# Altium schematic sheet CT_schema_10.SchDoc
size 251 x 159 mm
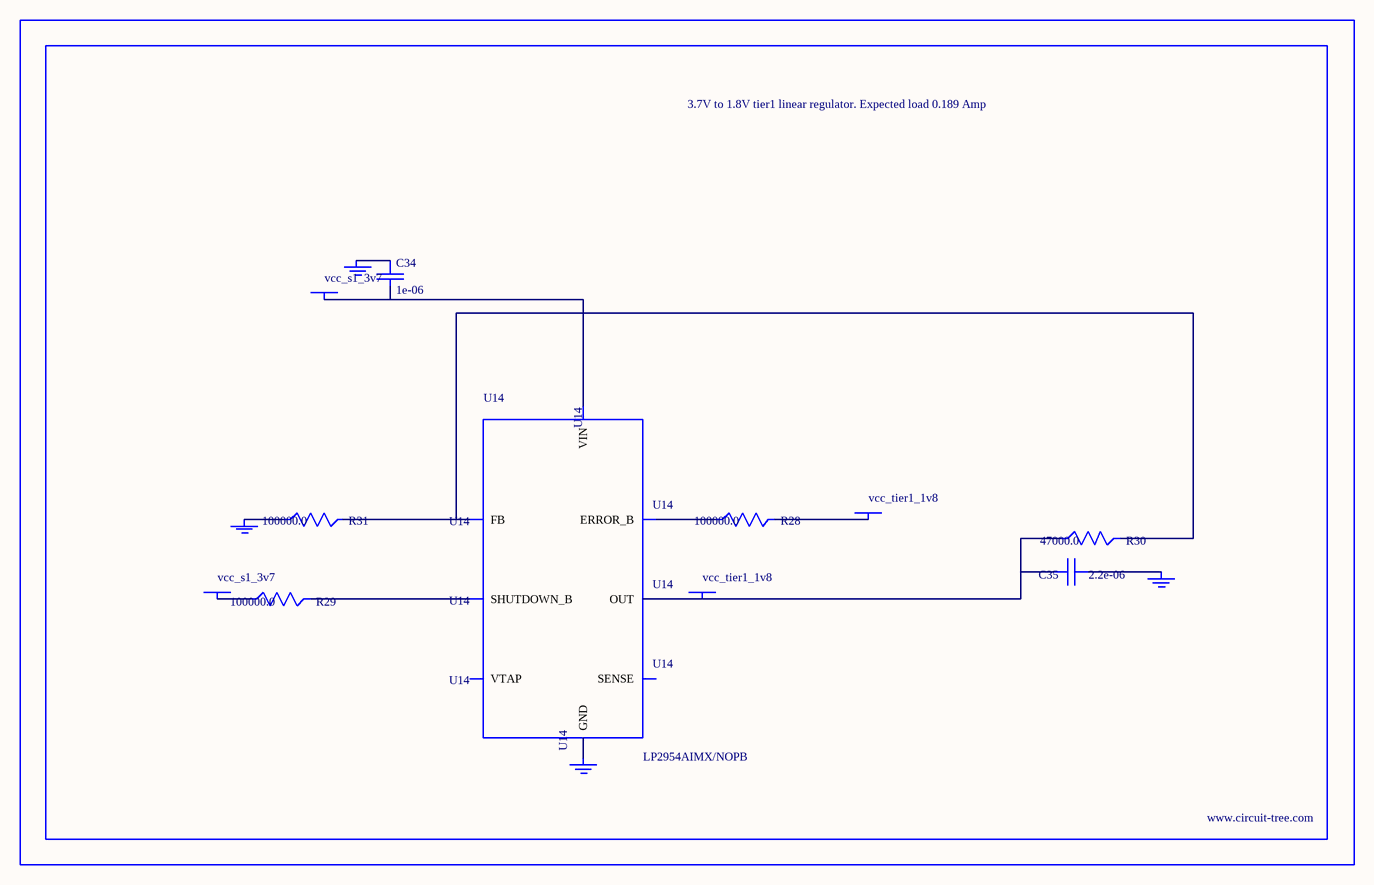
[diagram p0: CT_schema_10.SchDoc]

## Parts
BORDER9  (no value)
C34  1e-06  [EXV-9B]
C35  2.2e-06  [EXV-9B]
GND_INSTANCE_9_0  (no value)
GND_INSTANCE_9_1  (no value)
GND_INSTANCE_9_2  (no value)
GND_INSTANCE_9_3  (no value)
POWER_INSTANCE_9_0  vcc_s1_3v7
POWER_INSTANCE_9_1  vcc_tier1_1v8
POWER_INSTANCE_9_2  vcc_s1_3v7
POWER_INSTANCE_9_3  vcc_tier1_1v8
R28  100000.0  [R0603]
R29  100000.0  [R0603]
R30  47000.0  [R0603]
R31  100000.0  [R0603]
U14  LP2954AIMX/NOPB  [LP2954]

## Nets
NetC34_1: C34.1 GND_INSTANCE_9_2.0(GND)
NetC34_2: C34.2 POWER_INSTANCE_9_2.0(PWR) U14.8(VIN)
NetC35_1: C35.1 GND_INSTANCE_9_0.0(GND)
NetC35_2: C35.2 POWER_INSTANCE_9_3.0(PWR) R30.1 U14.1(OUT)
NetGND_INSTANCE_9_1_0: GND_INSTANCE_9_1.0(GND) R31.1
NetGND_INSTANCE_9_3_0: GND_INSTANCE_9_3.0(GND) U14.4(GND)
NetPOWER_INSTANCE_9_0_0: POWER_INSTANCE_9_0.0(PWR) R29.1
NetPOWER_INSTANCE_9_1_0: POWER_INSTANCE_9_1.0(PWR) R28.2
NetR28_1: R28.1 U14.5(ERROR_B)
NetR29_2: R29.2 U14.3(SHUTDOWN_B)
NetR30_2: R30.2 R31.2 U14.7(FB)

Not connected (* = marked no-connect by the designer): U14 2(SENSE) 6(VTAP)

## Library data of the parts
BORDER9 = BORDER_PAGE9
C34 = EDK105M050A9BAA
C35 = EDK225M050A9BAA
GND_INSTANCE_9_0-GND_INSTANCE_9_3 = GND
POWER_INSTANCE_9_0-POWER_INSTANCE_9_3 = PWR
R28 R29 R31 = RC0603JR-07100KL
R30 = RC0603JR-0747KL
